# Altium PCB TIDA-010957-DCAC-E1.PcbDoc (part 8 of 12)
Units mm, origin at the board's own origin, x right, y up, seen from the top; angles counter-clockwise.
Board outline 300 x 300 mm, 4 copper layers (Top Layer, Layer 1, Layer 2, Bottom Layer), stack 1.787 mm thick; 1159 components, 619 nets, 3431 pads, 2942 vias.
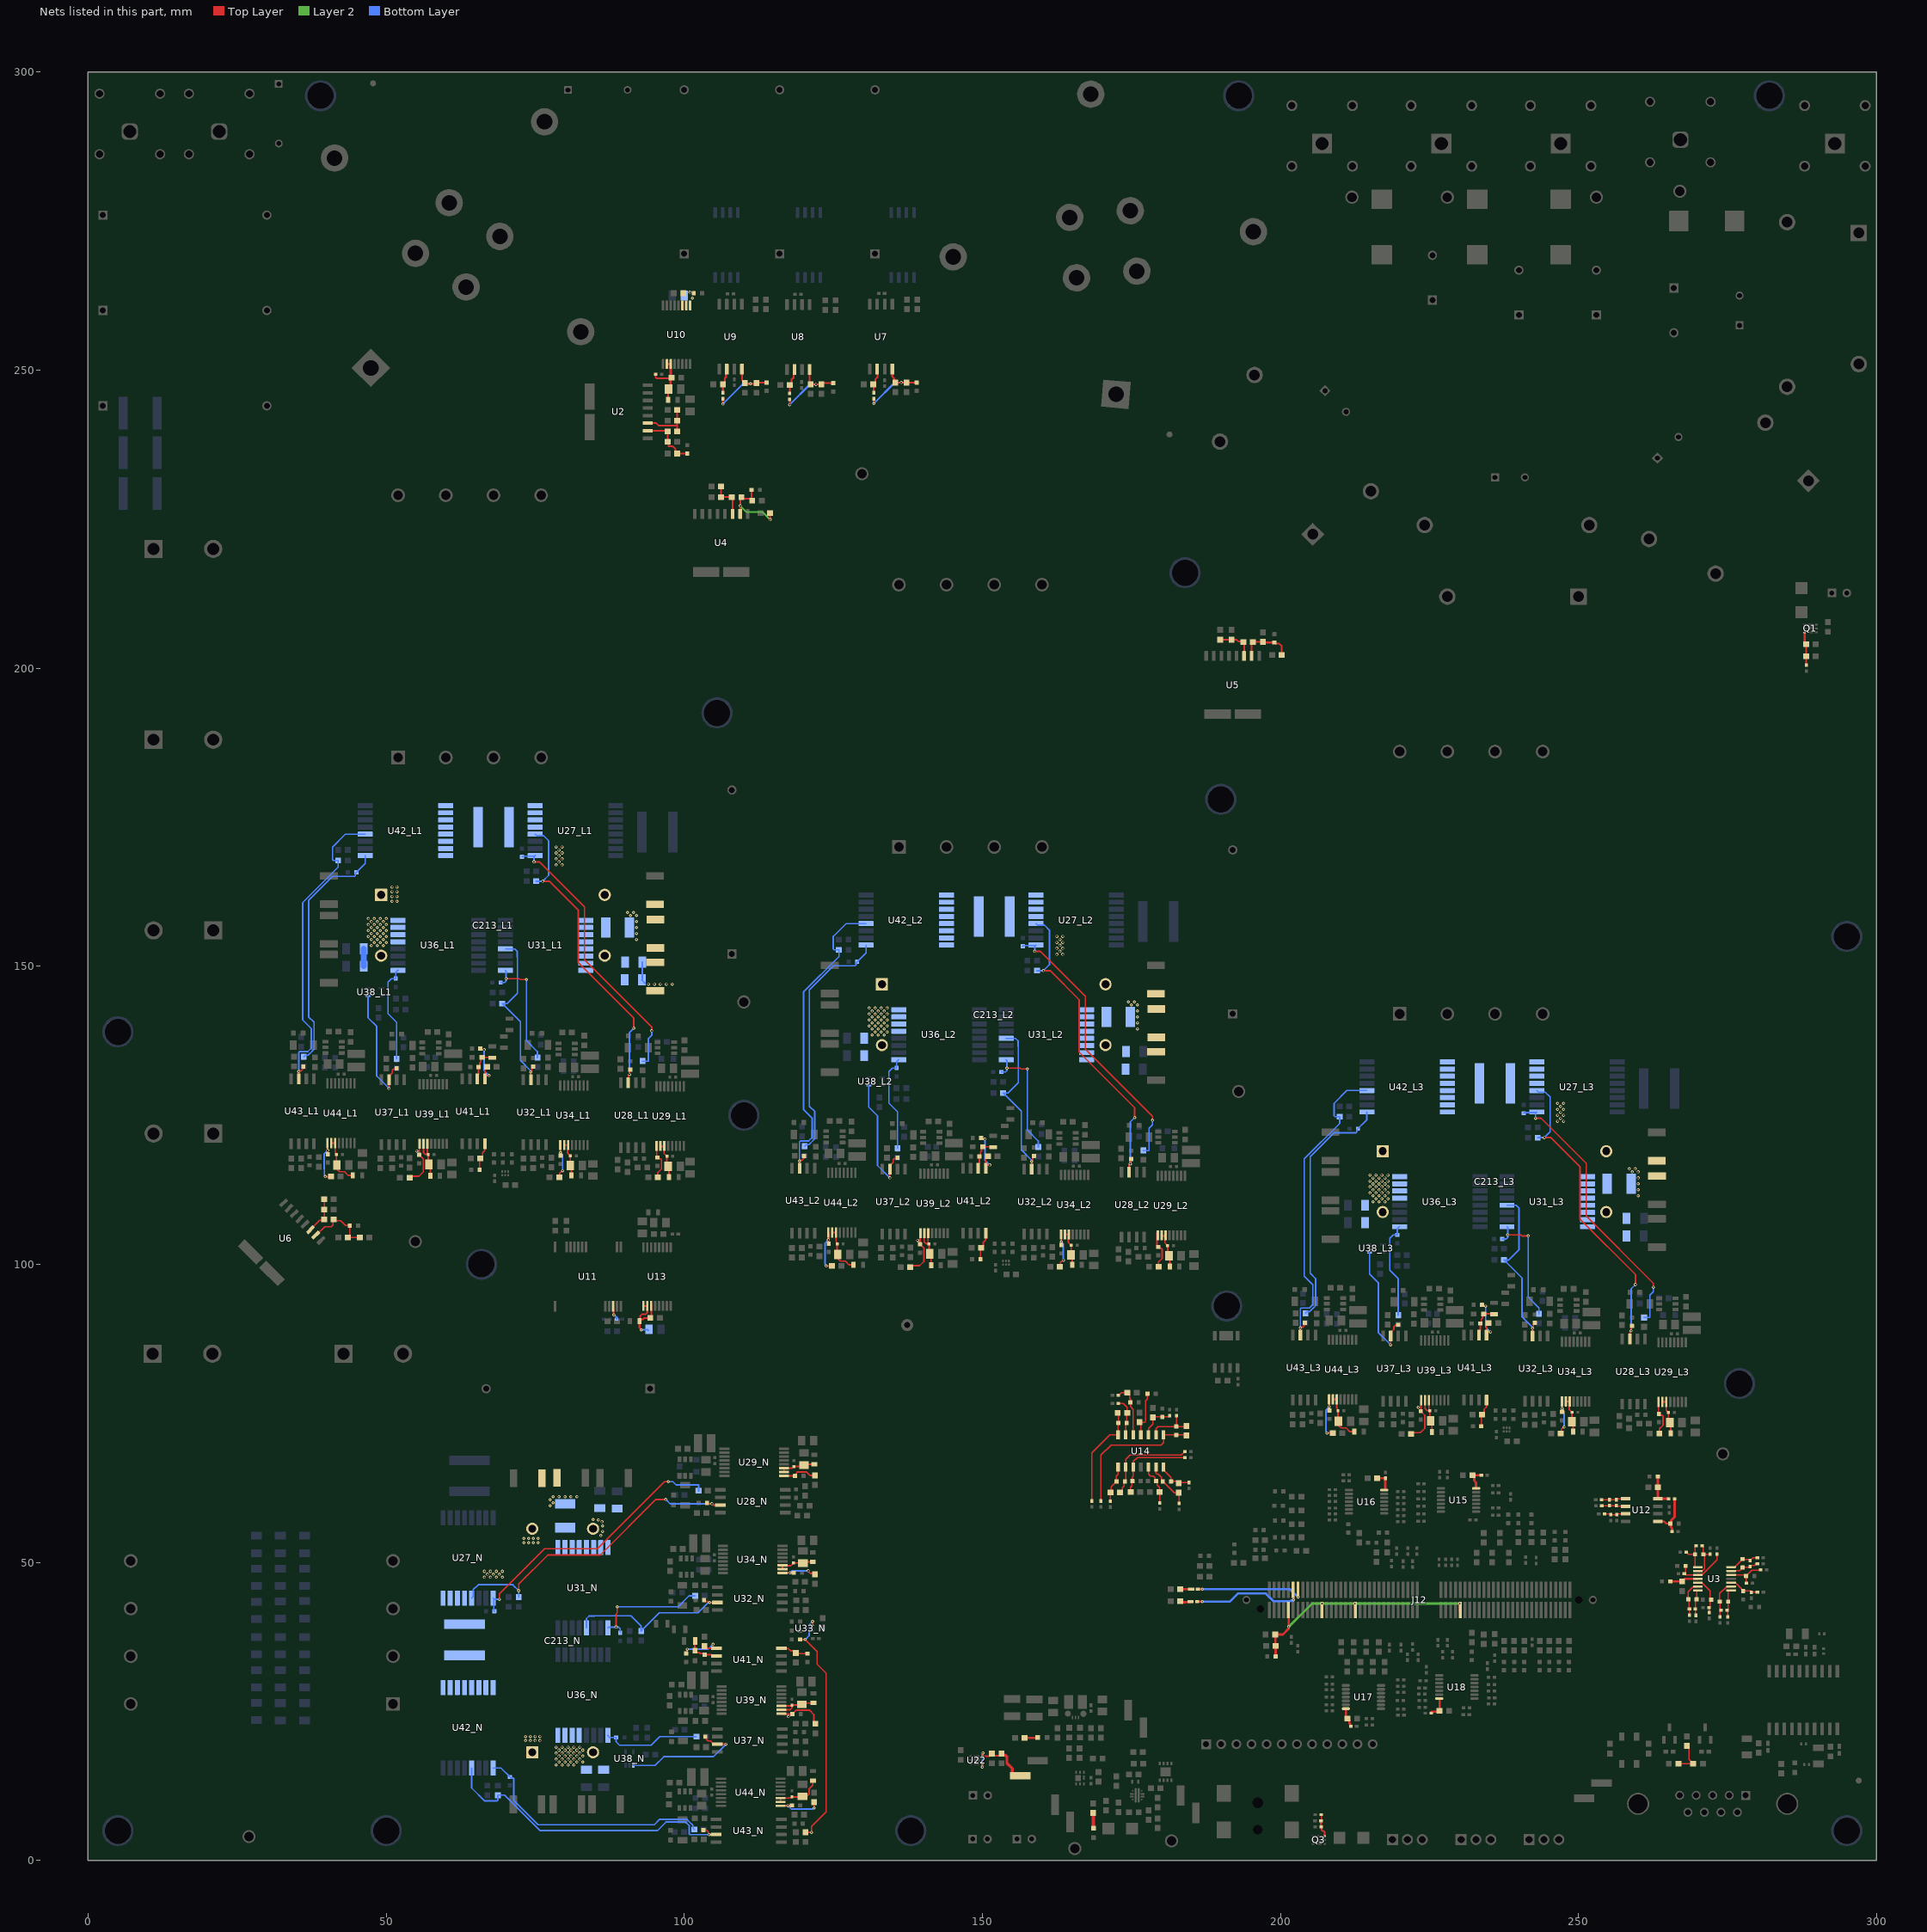
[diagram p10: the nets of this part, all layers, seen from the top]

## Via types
v1: diameter 0.508, hole 0.254, Top Layer to Bottom Layer, tented both sides, 2942 vias

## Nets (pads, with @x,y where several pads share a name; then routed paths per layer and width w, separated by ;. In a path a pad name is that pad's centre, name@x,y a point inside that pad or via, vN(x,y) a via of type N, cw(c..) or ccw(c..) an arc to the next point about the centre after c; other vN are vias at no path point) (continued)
MONITOR_S4_GaN_ISO_N: C206_N.2 R316_N.1 U33_N.6 | length 40.9
  Top Layer w0.254: C206_N.2@119.437,37.075 v1(120.276,37.075) 122.283,35.068 122.283,32.917 123.8,31.4 123.8,8.168 121.358,5.726 v1(121.358,4.718) 120.353,4.718 R316_N.1@120.345,4.725 ; U33_N.6@121.533,39.456 v1(121.533,40.084)
  Bottom Layer w0.254: v1(120.276,37.075) 120.335,37.075 120.936,37.676 120.936,39.488 v1(121.533,40.084)
NetC15_2: C15.2 C16.1 FB1.2 J12.48 J12.84 J12.98 J12.112 | length 42.9
  Top Layer w0.4: C15.2@199.1,37.9 200.4,37.9 201.4,38.9 v1(201.4,39.2) 201.4,41.1 J12.112@201.3,41.2 ; C15.2@199.15,37.85 199.15,36.05 C16.1@199.2,36 ; FB1.2@199.2,34.2 199.2,35.9 C16.1@199.4,36.1 ; J12.98@206.9,42 207,42.1 v1(207,43.1) ; v1(212.5,43.1) 212.525,43.075 212.525,42.025 J12.84@212.55,42 ; J12.48@230.1,41.7 v1(230.1,43.1)
  Layer 2 w0.4: v1(201.4,39.2) 205.3,43.1 v1(212.5,43.1) v1(230.1,43.1)
NetC28_1: C28.1 Q1.3 R96.2 R97.2 | length 5.8
  Top Layer w0.3: C28.1@287.9,204 287.93,204.03 Q1.3@287.93,206 ; R96.2@288.2,200.5 R97.2@288.2,202 288.2,204.1 C28.1@288.3,204.2
NetC29_1: C29.1 R98.1 R100.1 U3.5 | length 6.6
  Top Layer w0.2: U3.5@270,46.6 270.075,46.525 270.795,46.525 272.1,45.22 C29.1@272.1,43.6 ; R100.1@271.9,41.6 R98.1@271.9,42.4 271.95,42.4 272.1,42.55 272.1,43.578 C29.1@272.249,43.726
NetC30_1: C30.1 FB2.2 R99.2 R104.2 U2.4 | length 10.1
  Top Layer w0.3: U2.4@93.875,239.825 97.175,239.825 R104.2@97.3,239.7 ; R104.2@97.1,239.8 R104.2@97.2,239.7 C30.1@97.2,238 97.376,237.824 97.376,237.2 98.1,237.2 98.5,236.8 98.5,236.3 R99.2@98.8,236 FB2.2@100.5,236
NetC32_1: C32.1 R101.1 R103.1 U3.7 | length 4.5
  Top Layer w0.2: R101.1@269.65,40.997 269.65,43.625 C32.1@269.816,43.791 ; C32.1@269.8,43.791 269.8,45.225 269.875,45.3 U3.7@270,45.3
NetC32_2: C32.2 R102.1 R103.2 U3.6 | length 5.9
  Top Layer w0.2: C32.2@268.4,43.791 268.4,45.07 269.205,45.875 269.925,45.875 U3.6@270,45.95 ; C32.2@268.416,43.791 268.55,43.657 268.55,42.25 R103.2@268.6,42.2 R102.1@268.6,41.195
NetC34_1: C34.1 R104.1 R105.2 U2.5 | length 8.5
  Top Layer w0.3: U2.5@94,241.1 95.3,241.1 95.7,240.7 96.53,240.7 96.555,240.675 97.845,240.675 97.87,240.7 98.8,240.7 ; R104.1@98.8,239.7 98.8,240.7 ; C34.1@98.8,243.2 R105.2@98.8,241.5 98.8,240.7
NetC35_1: C35.1 R106.1 R107.1 U3.10 | length 5.2
  Top Layer w0.2: U3.10@275.6,46.6 275.675,46.525 276.395,46.525 277.367,45.552 277.367,45.432 C35.1@277.617,45.182 278.846,45.182 278.996,45.032 R106.1@278.996,44.985 279.011,45 R107.1@280,45
NetC36_1: C36.1 FB3.2 R109.2 R112.2 U4.4 | length 13.3
  Top Layer w0.3: U4.4@109.384,225.875 109.392,225.883 109.392,227.192 v1(109.4,227.2) R112.2@109.4,228.4 ; R112.2@109.5,228.4 111.1,228.4 C36.1@111.3,228.2 ; C36.1@111.2,228.1 C36.1@111.3,228.2 ; FB3.2@111.3,229.9 C36.1@111.3,228.2 ; v1(114.4,224.9) R109.2@114.4,226
  Layer 2 w0.3: v1(109.4,227.2) 110.4,226.2 113.1,226.2 v1(114.4,224.9)
NetC38_1: C38.1 R108.1 R111.1 U3.8 | length 5.1
  Top Layer w0.2: R111.1@274.863,41.95 275.063,42.15 275.063,43.383 C38.1@275.089,43.409 275.089,45.225 275.164,45.3 U3.8@275.6,45.3 ; R111.1@274.9,42 275.05,41.85 R108.1@275.05,40.863
NetC38_2: C38.2 R110.1 R111.2 U3.9 | length 6.3
  Top Layer w0.2: R110.1@273.75,40.863 273.75,43.349 C38.2@273.689,43.409 273.689,44.759 274.805,45.875 275.525,45.875 U3.9@275.6,45.95
NetC40_1: C40.1 R112.1 R113.2 U4.5 | length 6.6
  Top Layer w0.3: C40.1@105.9,230.6 106.2,230.3 R113.2@106.2,228.7 R112.1@108,228.7 ; U4.5@108.114,225.875 R112.1@108.114,228.7
NetC41_1: C41.1 R114.1 R115.1 U3.12 | length 6.7
  Top Layer w0.2: U3.12@275.6,47.9 277.919,47.9 C41.1@278.1,47.719 ; R114.1@278.185,46.5 278.1,46.585 C41.1@278.1,47.719 ; R115.1@280.567,48.7 279.081,48.7 C41.1@278.1,47.719
NetC42_1: C42.1 FB4.2 R117.2 R120.2 U5.4 | length 9.2
  Top Layer w0.3: U5.4@195.175,202.04 195.175,204.575 R120.2@195.3,204.7 ; R120.2@195.5,204.3 195.6,204.4 C42.1@197.1,204.4 ; C42.1@197.1,204.3 FB4.2@199,204.3 199.2,204.1 199.8,204.1 200.2,203.7 R117.2@200.2,202.2
NetC44_1: C44.1 R116.1 R119.1 U3.14 | length 5.3
  Top Layer w0.2: U3.14@275.6,49.2 276.225,49.2 276.3,49.275 276.3,49.313 C44.1@277.537,50.55 277.587,50.5 278.65,50.5 R119.1@278.8,50.35 ; R119.1@278.8,50.3 R119.1@278.8,50.35 ; R116.1@279.993,50.8 279.25,50.8 R119.1@278.8,50.35
NetC44_2: C44.2 R118.1 R119.2 U3.13 | length 4.9
  Top Layer w0.2: U3.13@275.6,48.55 275.675,48.625 277.012,48.625 C44.2@277.537,49.15 278.65,49.15 R119.2@278.8,49.3 278.8,49.35 278.95,49.5 279.496,49.5 279.746,49.75 R118.1@279.993,49.75
NetC46_1: C46.1 R120.1 R121.2 U5.5 | length 6.4
  Top Layer w0.3: R121.2@189.9,204.8 C46.1@191.8,204.8 192.6,204.8 192.9,204.5 R120.1@193.7,204.5 ; R120.1@193.8,204.4 193.905,204.295 U5.5@193.905,202.04 193.905,202.005 U5.5@193.9,202
NetC47_2: C47.2 FB5.2 U3.4 | length 4.8
  Top Layer w0.4: FB5.2@265.4,46.8 C47.2@267.4,46.8 267.4,46.825 267.825,47.25 U3.4@270,47.25
NetC48_1: C48.1 R122.1 R124.1 U3.3 | length 8.9
  Top Layer w0.2: R122.1@267.75,48.119 R122.1@267.8,48.119 ; C48.1@267.95,49.4 267.95,48.269 R122.1@267.8,48.119 ; R124.1@273.2,51.4 273.2,50.38 270.795,47.975 270.075,47.975 U3.3@270,47.9 268.019,47.9 R122.1@267.8,48.119
NetC49_1: C49.1 FB6.2 R123.2 R128.2 U6.4 | length 11.8
  Top Layer w0.2: U6.4@38.192,104.908 38.308,104.908 39.7,106.3 40.8,106.3 41.1,106.6 41.1,107.375 R128.2@41.225,107.5 41.425,107.3 42.4,107.3 43.2,106.5 FB6.2@43.9,106.5 43.9,104.8 R123.2@43.6,104.5 C49.1@45.6,104.5
NetC51_1: C51.1 R125.1 R127.1 U3.1 | length 5.8
  Top Layer w0.2: R125.1@268.05,51.684 268.1,51.684 268.438,51.346 C51.1@269.55,51.346 ; R127.1@269.75,52.807 269.7,52.807 269.55,52.657 269.55,52.607 C51.1@269.55,51.346 ; U3.1@270,49.2 269.625,49.2 269.55,49.275 C51.1@269.55,51.346
NetC51_2: C51.2 R126.1 R127.2 U3.2 | length 6.5
  Top Layer w0.2: U3.2@270,48.55 270.075,48.625 270.795,48.625 271.1,48.93 271.1,51.196 C51.2@270.95,51.346 ; R127.2@270.75,52.807 270.8,52.807 270.95,52.657 C51.2@270.95,51.346 ; R126.1@272.1,51.4 272.046,51.346 C51.2@270.95,51.346
NetC53_1: C53.1 R128.1 R129.2 U6.5 | length 6.4
  Top Layer w0.2: U6.5@37.294,105.807 38.875,107.387 39.512,107.387 R128.1@39.625,107.5 C53.1@39.625,110.9
NetC56_2: C56.2 C57.1 FB7.1 R131.2 U7.8 | length 12.9
  Top Layer w0.3: v1(131.8,244.4) R131.2@131.8,245.2 ; U7.8@134.91,250.15 134.91,248.89 135.2,248.6 C56.2@135.2,247.87 ; C56.2@135.4,247.8 135.5,247.9 v1(136.4,247.9) 137,247.9 FB7.1@139,247.9
  Bottom Layer w0.3: v1(131.8,244.4) 135.3,247.9 v1(136.4,247.9)
NetC60_1: C60.1 R131.1 U7.6 | length 3.8
  Top Layer w0.3: R131.1@131.8,246.2 131.8,247.5 C60.1@131.9,247.6 ; C60.1@131.812,247.687 132.05,247.925 132.05,248.45 132.4,248.8 U7.6@132.4,249.8
NetC63_2: C63.2 C64.1 FB8.1 R133.2 U8.8 | length 12.3
  Top Layer w0.3: v1(117.7,244.2) R133.2@117.7,245.1 ; C63.2@121,247.8 121.04,247.84 U8.8@121.04,250.1 ; C63.2@121.5,247.6 v1(122.1,247.6) ; v1@122.2,247.6 123.017,247.6 C64.1@123.02,247.602 ; C64.1@123.1,247.8 FB8.1@125,247.8
  Bottom Layer w0.3: v1(117.7,244.2) 121.1,247.6 v1(122.1,247.6)
NetC67_1: C67.1 R133.1 U8.6 | length 4.2
  Top Layer w0.3: R133.1@117.7,246.1 C67.1@117.7,247.5 118,247.8 118,248.424 118.176,248.6 118.224,248.6 118.374,248.75 118.374,249.674 U8.6@118.6,249.9
NetC70_2: C70.2 C71.1 FB9.1 R135.2 U9.8 | length 12.6
  Top Layer w0.3: v1(106.5,244.3) 106.5,245.1 R135.2@106.6,245.2 ; U9.8@109.675,250.15 109.675,248.35 110.2,247.825 C70.2@110.2,247.8 ; C70.2@110.5,247.8 110.5,247.725 110.525,247.7 v1(111.1,247.7) C71.1@111.8,247.7 ; C71.1@112.4,247.7 112.4,247.875 112.425,247.9 FB9.1@113.8,247.9
  Bottom Layer w0.3: v1(106.5,244.3) 109.9,247.7 v1(111.1,247.7) v1@111.2,247.7
NetC74_1: C74.1 R135.1 U9.6 | length 3.9
  Top Layer w0.3: R135.1@106.5,246.2 106.5,247.4 C74.1@106.7,247.6 ; C74.1@106.612,247.688 106.85,247.925 106.85,248.65 106.999,248.799 106.999,249.799 U9.6@107.1,249.9
NetC75_1: C75.1 C76.1 FB10.2 U10.9 U10.10 U10.11
  other v1: 101.375,262.079 100.966,263.045
NetC77_1: C77.1 C78.1 L7.1 R136.1 U10.2 U10.3 | length 10
  Top Layer w0.2: C77.1@97.75,248.85 C77.1@97.9,248.7
  Top Layer w0.3: R136.1@95.1,249.3 95.2,249.2 95.2,248.776 95.376,248.6 C77.1@97.7,248.6 ; L7.1@97.3,245 C78.1@97.3,246.6 ; C78.1@97.384,246.8 97.7,247.116 C77.1@97.7,248.6 ; C77.1@97.7,248.7 C77.1@97.7,248.6 ; C77.1@97.9,248.7 97.8,248.6 C77.1@97.7,248.6
  Top Layer w0.4: U10.2@97.1,251 U10.3@97.75,251 C77.1@97.75,248.85
NetC82_1: C82.1 FB16.1 R331.1 U12.8 | length 5.5
  Top Layer w0.45: FB16.1@263.3,64.4 C82.1@263.3,62.6 U12.8@263.3,60.68 R331.1@265.121,60.68
NetC83_2: C83.2 R137.1 R139.1 U12.3 | length 3.6
  Top Layer w0.2: R139.1@254.383,58.14 255.26,58.14 C83.2@255.4,58 R137.1@256.4,58 256.54,58.14 U12.3@257.9,58.14
NetC85_2: C85.2 U11.4 | length 2
  Top Layer w0.3: U11.4@88.154,92.5 88.141,92.486 88.141,91.559 v1(88.2,91.5)
  Bottom Layer w0.3: v1(88.2,91.5) 88.284,91.5 88.684,91.1 88.684,90.816 C85.2@88.7,90.8
NetC86_1: C86.1 R141.1 R142.1 U12.2 | length 4.1
  Top Layer w0.2: R141.1@253.9,59.5 255.477,59.5 ; C86.1@255.405,59.513 R142.1@256.35,59.513 256.453,59.41 U12.2@257.9,59.41
NetC86_2: C86.2 R140.1 R142.2 U12.1 | length 4.2
  Top Layer w0.2: R140.1@253.883,60.513 255.49,60.513 ; C86.2@255.405,60.513 R142.2@256.35,60.513 ; R142.2@256.35,60.53 256.5,60.68 U12.1@257.9,60.68
NetC89_1: C89.1 C90.1 L8.1 U13.9 U13.10 U13.11 | length 10.5
  Top Layer w0.3: v1(92.8,89) 92.8,89.084 92.5,89.384 L8.1@92.5,90.5 92.632,90.632 L8.1@92.632,90.71 ; U13.9@93.163,93.004 93.796,93.004 U13.10@93.8,93 ; U13.10@93.8,92.6 93.8,91.9 93.5,91.6 92.884,91.6 92.632,91.348 L8.1@92.632,90.71 ; C90.1@94.3,91 93.33,91 93.108,90.778 92.7,90.778 L8.1@92.632,90.71 ; C90.1@94.313,91.033 94.5,91.22 U13.11@94.5,93.2
  Bottom Layer w0.3: v1(92.8,89) 93.9,89 C89.1@94,88.9
NetC94_1: C94.1 FB11.2 U14.4 | length 8
  Top Layer w0.2: U14.4@176.586,71.384 176.586,73.269 176.426,73.429 176.497,73.5 177.283,73.5 177.4,73.617 177.4,77.1 177.7,77.4 FB11.2@177.7,78.3
NetC95_2: C95.2 R144.1 R145.1 U14.3 | length 6.2
  Top Layer w0.2: U14.3@177.856,71.384 177.856,72.456 178.6,73.2 R144.1@178.6,74.3 178.7,74.4 C95.2@180.2,74.4 180.204,74.404 181.278,74.404 181.428,74.554 R145.1@181.428,74.604
NetC97_1: C97.1 R147.1 R148.2 U14.2 | length 8.2
  Top Layer w0.2: U14.2@179.126,71.384 179.126,72.426 179.5,72.8 182.503,72.8 C97.1@182.519,72.784 ; R147.1@182.59,74.609 182.59,72.854 C97.1@182.519,72.784 ; R148.2@184.209,72.884 184.109,72.784 C97.1@182.519,72.784
NetC97_2: C97.2 R146.1 R148.1 U14.1 | length 24.1
  Top Layer w0.2: R146.1@169.9,60.3 169.9,68 171.6,69.7 180,69.7 180.396,70.096 U14.1@180.396,71.384 C97.2@182.519,71.384 R148.1@184.109,71.384
NetC98_2: C98.2 R149.1 R150.1 U14.5 | length 9.2
  Top Layer w0.2: R150.1@172.82,78 172.87,78 173.345,78.475 R149.1@174.291,78.475 174.316,78.475 174.691,78.1 174.691,77.509 174.832,77.368 C98.2@174.832,76.829 174.832,76.168 175.316,75.684 U14.5@175.316,71.384
NetC100_1: C100.1 R152.1 R153.2 U14.6 | length 6.5
  Top Layer w0.2: R152.1@172.82,76.663 173.637,76.663 174.295,76.005 R153.2@174.295,75.051 174.215,74.971 C100.1@174.215,73.401 174.046,73.232 U14.6@174.046,71.384
NetC100_2: C100.2 R151.1 R153.1 U14.7 | length 17.5
  Top Layer w0.2: R151.1@168.4,60.244 168.4,68.4 171.384,71.384 U14.7@172.776,71.384 172.776,73.362 C100.2@172.815,73.401 172.815,74.931 R153.1@172.695,75.051
NetC101_2: C101.2 R154.1 R155.1 U14.10 | length 14.3
  Top Layer w0.2: R154.1@174.873,61.784 174.873,62.573 175.1,62.8 175.1,63.549 C101.2@175.176,63.625 175.176,64.276 175.316,64.416 U14.10@175.316,65.984 175.316,66.916 176,67.6 R155.1@184,67.6
NetC103_1: C103.1 R157.1 R158.2 U14.9 | length 16.4
  Top Layer w0.2: R158.2@173.12,61.741 173.125,61.741 173.5,62.116 173.5,62.5 173.8,62.8 173.8,63.462 C103.1@173.92,63.583 174.046,63.709 U14.9@174.046,65.984 174.1,66.037 174.1,67.3 174.8,68 183.4,68 R157.1@184,68.6
NetC103_2: C103.2 R156.1 R158.1 U14.8 | length 6.3
  Top Layer w0.2: R156.1@171.457,60.275 171.457,61.678 R158.1@171.52,61.741 171.6,61.821 171.6,62.662 C103.2@172.52,63.583 172.5,63.603 172.5,64.5 172.776,64.776 U14.8@172.776,65.984
NetC104_2: C104.2 R159.1 R160.1 U14.12 | length 7.1
  Top Layer w0.2: U14.12@177.856,65.984 177.856,64.844 178.2,64.5 178.7,64.5 179,64.2 179,63.782 C104.2@179.157,63.625 179.358,63.424 179.358,62.942 179.7,62.6 R159.1@179.7,61.8 179.765,61.735 R160.1@179.765,59.975
NetC106_1: C106.1 R162.1 R163.2 U14.13 | length 8.3
  Top Layer w0.2: U14.13@179.126,65.984 179.126,64.917 179.243,64.8 179.5,64.8 180.06,64.24 180.06,63.784 C106.1@180.261,63.583 182.195,61.648 183,61.648 R162.1@183,59.9
NetC106_2: C106.2 R161.1 R163.1 U14.14 | length 6.2
  Top Layer w0.2: U14.14@180.396,65.984 180.396,65.509 180.9,65.005 180.9,65 181.661,64.239 C106.2@181.661,63.583 ; C106.2@181.6,63.521 C106.2@181.661,63.583 ; R161.1@184.7,63.4 183.031,63.4 R163.1@182.94,63.309 182.666,63.583 C106.2@181.661,63.583
NetC107_1: C107.1 R164.1 U15.14 | length 3.9
  Top Layer w0.4: C107.1@232.2,64.6 C107.1@232.225,64.6 ; U15.14@232.821,62.402 232.821,63.379 232.5,63.7 232.5,64.325 C107.1@232.225,64.6 ; R164.1@233.7,64.6 C107.1@232.225,64.6
NetC113_1: C113.1 R174.1 U16.14 | length 3.2
  Top Layer w0.4: C113.1@216.2,64.1 R174.1@217.5,64.1 ; U16.14@217.6,62.2 R174.1@217.6,64.1
NetC114_1: C114.1 R175.1 U17.14 | length 3
  Top Layer w0.4: U17.14@211,25.3 211,24.048 C114.1@211.266,23.781 ; C114.1@211.4,23.7 211.566,23.534 211.566,23.034 211.7,22.9 211.7,22.55 211.75,22.5 R175.1@211.8,22.5
NetC125_1: C125.1 R194.1 U18.14 | length 3.4
  Top Layer w0.4: R194.1@225.3,24.9 225.35,24.95 C125.1@226.65,24.95 ; C125.1@226.7,25.1 U18.14@226.7,27.1
NetC138_1: C138.1 C144.1 J18.2 U22.4 U22.6 | length 12.9
  Top Layer w0.2: v1@149.975,15.626 v1(150,15.651) 150.025,15.676 U22.4@150.025,16.176 ; U22.6@150.025,17.476 150.025,17.951 v1(150.1,18.026) ; C144.1@151.287,17.562 151.6,17.875 C144.1@151.6,17.9 ; J18.2@155.293,14.205 J18.2@156.373,14.205
  Top Layer w0.3: U22.4@150.025,16.176 U22.4@150.1,16.176 ; U22.6@150.025,17.476 151.201,17.476 151.287,17.562 C138.1@152.862,17.562
  Top Layer w0.5: C138.1@153.2,17.9 153.2,17.875 153.425,17.65 153.832,17.65 154.125,17.357 154.125,16.3 155,15.425 155,14.498 J18.2@155.293,14.205
  Bottom Layer w0.2: v1(150,15.651) 150,17.842 150.1,17.942 v1(150.1,18.026)
NetC157_2: C157.2 R226.1 R227.2 | length 5.9
  Top Layer w0.2: R226.1@266.75,16.25 R227.2@269.225,16.25 ; C157.2@268.2,19.2 268.526,18.874 268.526,16.949 R227.2@269.225,16.25 ; R227.2@269.25,16.25 R227.2@269.225,16.25
NetC188_L1_2: C188_L1.2 R279_L1.2 U27_L1.9 | length 46.6
  Top Layer w0.254: v1(74.8,167.5) 75.725,167.5 83.288,159.937 83.288,151.073 94.55,139.811 v1(94.55,139.151)
  Bottom Layer w0.254: C188_L1.2@72.801,168.347 72.903,168.448 U27_L1.9@74.898,168.448 ; v1(74.8,167.5) 74.8,168.35 U27_L1.9@74.898,168.448 ; U27_L1.9@75,168.55 U27_L1.9@74.898,168.448 ; R279_L1.2@93,134.073 93.007,134.066 93.975,134.066 93.975,137.834 94.55,138.409 v1(94.55,139.151)
NetC188_L2_2: C188_L2.2 R279_L2.2 U27_L2.9 | length 46.6
  Top Layer w0.254: v1(158.8,152.5) 159.725,152.5 167.288,144.937 167.288,136.073 178.55,124.811 v1(178.55,124.151)
  Bottom Layer w0.254: C188_L2.2@156.801,153.347 156.903,153.448 U27_L2.9@158.898,153.448 ; v1(158.8,152.5) 158.8,153.35 U27_L2.9@158.898,153.448 ; U27_L2.9@159,153.55 U27_L2.9@158.898,153.448 ; R279_L2.2@177,119.073 177.007,119.066 177.975,119.066 177.975,122.834 178.55,123.409 v1(178.55,124.151)
NetC188_L3_2: C188_L3.2 R279_L3.2 U27_L3.9 | length 46.6
  Top Layer w0.254: v1(242.8,124.5) 243.725,124.5 251.288,116.937 251.288,108.073 262.55,96.811 v1(262.55,96.151)
  Bottom Layer w0.254: C188_L3.2@240.801,125.347 240.903,125.448 U27_L3.9@242.898,125.448 ; v1(242.8,124.5) 242.8,125.35 U27_L3.9@242.898,125.448 ; U27_L3.9@243,125.55 U27_L3.9@242.898,125.448 ; R279_L3.2@261,91.073 261.007,91.066 261.975,91.066 261.975,94.834 262.55,95.409 v1(262.55,96.151)
NetC188_N_2: C188_N.2 R279_N.2 U27_N.9 | length 46.6
  Top Layer w0.254: v1(69,43.8) 69,44.725 76.563,52.288 85.427,52.288 96.689,63.55 v1(97.349,63.55)
  Bottom Layer w0.254: U27_N.9@67.95,44 U27_N.9@68.052,43.898 ; C188_N.2@68.153,41.801 68.052,41.903 U27_N.9@68.052,43.898 ; v1(69,43.8) 68.15,43.8 U27_N.9@68.052,43.898 ; v1(97.349,63.55) 98.091,63.55 98.666,62.975 102.434,62.975 102.434,62.007 R279_N.2@102.427,62
NetC189_L1_2: C189_L1.2 R283_L1.2 U27_L1.12 U28_L1.7 | length 53.1
  Top Layer w0.254: v1(76.253,164.25) 77.373,164.25 82.247,159.376 82.247,150.577 91.55,141.273 v1(91.55,139.6) ; U28_L1.7@90.615,130.45 90.615,131.636 v1(90.825,131.846) 90.825,132.524 C189_L1.2@90.967,132.666
  Bottom Layer w0.254: U27_L1.12@75,172.15 75.263,171.887 76.413,171.887 77.25,171.05 77.25,165.247 v1(76.253,164.25) R283_L1.2@75.151,164.25 ; v1(90.825,131.846) 90.825,138.875 v1(91.55,139.6)
NetC189_L2_2: C189_L2.2 R283_L2.2 U27_L2.12 U28_L2.7 | length 53.1
  Top Layer w0.254: v1(160.253,149.25) 161.373,149.25 166.247,144.376 166.247,135.577 175.55,126.273 v1(175.55,124.6) ; U28_L2.7@174.615,115.45 174.615,116.636 v1(174.825,116.846) 174.825,117.524 C189_L2.2@174.967,117.666
  Bottom Layer w0.254: U27_L2.12@159,157.15 159.263,156.887 160.413,156.887 161.25,156.05 161.25,150.247 v1(160.253,149.25) R283_L2.2@159.151,149.25 ; v1(174.825,116.846) 174.825,123.875 v1(175.55,124.6)
NetC189_L3_2: C189_L3.2 R283_L3.2 U27_L3.12 U28_L3.7 | length 53.1
  Top Layer w0.254: v1(244.253,121.25) 245.373,121.25 250.247,116.376 250.247,107.577 259.55,98.273 v1(259.55,96.6) ; U28_L3.7@258.615,87.45 258.615,88.636 v1(258.825,88.846) 258.825,89.524 C189_L3.2@258.967,89.666
  Bottom Layer w0.254: U27_L3.12@243,129.15 243.263,128.887 244.413,128.887 245.25,128.05 245.25,122.247 v1(244.253,121.25) R283_L3.2@243.151,121.25 ; v1(258.825,88.846) 258.825,95.875 v1(259.55,96.6)
NetC189_N_2: C189_N.2 R283_N.2 U27_N.12 U28_N.7 | length 53.1
  Top Layer w0.254: v1(72.25,45.253) 72.25,46.373 77.124,51.247 85.923,51.247 95.227,60.55 v1(96.9,60.55) ; C189_N.2@103.834,59.967 103.976,59.825 v1(104.654,59.825) 104.864,59.615 U28_N.7@106.05,59.615
  Bottom Layer w0.254: U27_N.12@64.35,44 64.613,44.263 64.613,45.413 65.45,46.25 71.253,46.25 v1(72.25,45.253) R283_N.2@72.25,44.151 ; v1(96.9,60.55) 97.625,59.825 v1(104.654,59.825)
NetC196_L1_2: C196_L1.2 R287_L1.1 U29_L1.1 | length 6
  Top Layer w0.254: U29_L1.1@95.375,119.855 95.375,118.027 95.72,117.682 96.011,117.682 96.174,117.519 96.174,115.995 95.563,115.383 R287_L1.1@95.563,114.583
NetC196_L2_2: C196_L2.2 R287_L2.1 U29_L2.1 | length 6.5
  Top Layer w0.254: U29_L2.1@179.3,105.311 179.3,103.102 179.72,102.682 180.011,102.682 180.174,102.519 180.174,100.995 179.563,100.383 R287_L2.1@179.563,99.583
NetC196_L3_2: C196_L3.2 R287_L3.1 U29_L3.1 | length 6.2
  Top Layer w0.254: U29_L3.1@263.425,76.9 C196_L3.2@263.425,74.977 ; C196_L3.2@263.497,74.905 C196_L3.2@263.425,74.977 ; R287_L3.1@263.563,71.583 263.563,72.383 264.174,72.995 264.174,74.519 264.011,74.682 263.72,74.682 C196_L3.2@263.425,74.977
NetC196_N_2: C196_N.2 R287_N.1 U29_N.1 | length 5.9
  Top Layer w0.254: U29_N.1@116.75,64.497 C196_N.2@118.595,64.497 118.818,64.72 118.818,65.011 118.981,65.174 120.505,65.174 121.117,64.563 R287_N.1@121.917,64.563
NetC198_L1_1: C198_L1.1 C199_L1.2 L11_L1.1 U29_L1.2 U29_L1.3 | length 5.5
  Top Layer w0.254: U29_L1.2@96.147,119.75 96.622,119.75 96.622,118.596 C199_L1.2@97.088,118.13 97.088,116.964 97.322,116.73 97.463,116.589 L11_L1.1@97.463,115.058
NetC198_L2_1: C198_L2.1 C199_L2.2 L11_L2.1 U29_L2.2 U29_L2.3 | length 5.5
  Top Layer w0.254: U29_L2.2@180.147,104.75 180.622,104.75 180.622,103.596 C199_L2.2@181.088,103.13 181.088,101.964 181.322,101.73 181.463,101.589 L11_L2.1@181.463,100.058
NetC198_L3_1: C198_L3.1 C199_L3.2 L11_L3.1 U29_L3.2 U29_L3.3 | length 5.8
  Top Layer w0.254: U29_L3.2@264.147,76.75 264.147,76.894 264.153,76.9 264.647,76.9 264.707,76.84 264.707,75.511 C199_L3.2@265.088,75.13 265.088,73.964 265.322,73.73 265.463,73.589 L11_L3.1@265.463,72.058
NetC198_N_1: C198_N.1 C199_N.2 L11_N.1 U29_N.2 U29_N.3 | length 5.6
  Top Layer w0.254: U29_N.2@116.75,65.147 U29_N.3@116.75,65.797 116.759,65.788 118.07,65.788 C199_N.2@118.37,66.088 119.536,66.088 119.77,66.322 119.911,66.463 L11_N.1@121.442,66.463
NetC202_L1_2: C202_L1.2 R292_L1.2 U31_L1.9 | length 20.2
  Top Layer w0.254: v1(70.127,147.925) 72.33,147.925 72.505,147.75 v1(73.55,147.75)
  Bottom Layer w0.254: C202_L1.2@69.207,147.25 69.873,147.25 70.127,147.504 v1(70.127,147.925) 70.127,149.173 U31_L1.9@70,149.3 ; v1(73.55,147.75) 73.55,137.51 75.385,135.675 R292_L1.2@75.385,134.682
NetC202_L2_2: C202_L2.2 R292_L2.2 U31_L2.9 | length 20.2
  Top Layer w0.254: v1(154.127,132.925) 156.33,132.925 156.505,132.75 v1(157.55,132.75)
  Bottom Layer w0.254: C202_L2.2@153.207,132.25 153.873,132.25 154.127,132.504 v1(154.127,132.925) 154.127,134.173 U31_L2.9@154,134.3 ; v1(157.55,132.75) 157.55,122.51 159.385,120.675 R292_L2.2@159.385,119.682
NetC202_L3_2: C202_L3.2 R292_L3.2 U31_L3.9 | length 20.2
  Top Layer w0.254: v1(238.127,104.925) 240.33,104.925 240.505,104.75 v1(241.55,104.75)
  Bottom Layer w0.254: C202_L3.2@237.207,104.25 237.873,104.25 238.127,104.504 v1(238.127,104.925) 238.127,106.173 U31_L3.9@238,106.3 ; v1(241.55,104.75) 241.55,94.51 243.385,92.675 R292_L3.2@243.385,91.682
NetC202_N_2: C202_N.2 R292_N.2 U31_N.9 | length 20.2
  Top Layer w0.254: v1(88.575,39.127) 88.575,41.33 88.75,41.505 v1(88.75,42.55)
  Bottom Layer w0.254: U31_N.9@87.2,39 87.327,39.127 v1(88.575,39.127) 88.996,39.127 89.25,38.873 C202_N.2@89.25,38.207 ; v1(88.75,42.55) 98.99,42.55 100.825,44.385 R292_N.2@101.818,44.385
NetC203_L1_2: C203_L1.2 R294_L1.2 U31_L1.12 U32_L1.7 | length 28.3
  Top Layer w0.254: U32_L1.7@74.275,130.95 v1(74.275,132.253) 74.275,132.321 74.437,132.483 74.437,132.959 C203_L1.2@74.66,133.182
  Bottom Layer w0.254: R294_L1.2@69.49,143.725 R294_L1.2@69.515,143.725 ; U31_L1.12@70,152.9 71.573,152.9 72,152.473 72,151.523 72.031,151.492 72.031,145.453 70.303,143.725 R294_L1.2@69.515,143.725 ; v1(74.275,132.253) 74.275,132.436 72.53,134.181 72.53,140.685 69.863,143.352 69.863,143.377 R294_L1.2@69.515,143.725
NetC203_L2_2: C203_L2.2 R294_L2.2 U31_L2.12 U32_L2.7 | length 28.3
  Top Layer w0.254: U32_L2.7@158.275,115.95 v1(158.275,117.253) 158.275,117.321 158.437,117.483 158.437,117.959 C203_L2.2@158.66,118.182
  Bottom Layer w0.254: R294_L2.2@153.49,128.725 R294_L2.2@153.515,128.725 ; U31_L2.12@154,137.9 155.573,137.9 156,137.473 156,136.523 156.031,136.492 156.031,130.453 154.303,128.725 R294_L2.2@153.515,128.725 ; v1(158.275,117.253) 158.275,117.436 156.53,119.181 156.53,125.685 153.863,128.352 153.863,128.377 R294_L2.2@153.515,128.725
NetC203_L3_2: C203_L3.2 R294_L3.2 U31_L3.12 U32_L3.7 | length 28.3
  Top Layer w0.254: U32_L3.7@242.275,87.95 v1(242.275,89.253) 242.275,89.321 242.437,89.483 242.437,89.959 C203_L3.2@242.66,90.182
  Bottom Layer w0.254: R294_L3.2@237.49,100.725 R294_L3.2@237.515,100.725 ; U31_L3.12@238,109.9 239.573,109.9 240,109.473 240,108.523 240.031,108.492 240.031,102.453 238.303,100.725 R294_L3.2@237.515,100.725 ; v1(242.275,89.253) 242.275,89.436 240.53,91.181 240.53,97.685 237.863,100.352 237.863,100.377 R294_L3.2@237.515,100.725
NetC203_N_2: C203_N.2 R294_N.2 U31_N.12 U32_N.7 | length 28.3
  Top Layer w0.254: C203_N.2@103.318,43.66 103.541,43.437 104.017,43.437 104.179,43.275 v1(104.247,43.275) U32_N.7@105.55,43.275
  Bottom Layer w0.254: U31_N.12@83.6,39 83.6,40.573 84.027,41 84.977,41 85.008,41.031 91.047,41.031 92.775,39.303 R294_N.2@92.775,38.515 ; R294_N.2@92.775,38.49 R294_N.2@92.775,38.515 ; v1(104.247,43.275) 104.064,43.275 102.319,41.53 95.815,41.53 93.148,38.863 93.123,38.863 R294_N.2@92.775,38.515
NetC213_L1_1: C213_L1.1 C215_L1.1 C216_L1.2 R319_L1.2 R320_L1.2 U36_L1.13 U36_L1.14 U36_L1.15 U36_L1.16 U42_L1.1 U42_L1.2 U42_L1.3 U42_L1.4 U42_L1.5 U42_L1.6 U42_L1.7 U42_L1.8 | length 2.9
  Bottom Layer w1: R319_L1.2@46.219,150 R320_L1.2@46.219,152.9
  other v1: 47.525,153.475 48.525,153.475 49.525,153.475 48.025,153.975 49.025,153.975 50.025,153.975 47.525,154.475 48.525,154.475 49.525,154.475 92,154.5 47.025,154.975 48.025,154.975 49.025,154.975 50.025,154.975 47.525,155.475 48.525,155.475 49.525,155.475 92,155.5 47.025,155.975 48.025,155.975 49.025,155.975 50.025,155.975 47.525,156.475 48.525,156.475 49.525,156.475 92,156.5 47.025,156.975 48.025,156.975 49.025,156.975 50.025,156.975 47.525,157.475 48.525,157.475 49.525,157.475 92,157.5 47.025,157.975 48.025,157.975 49.025,157.975 50.025,157.975 91,158.5 92,158.5 90.5,159 91.5,159 51,160.9 51.8,160.9 51,161.7 51.8,161.7 51,162.5 51.8,162.5 51,163.3 51.8,163.3
NetC213_L1_2: C213_L1.2 C215_L1.2 C216_L1.1 R281_L1.1 R282_L1.1 U27_L1.13 U27_L1.14 U27_L1.15 U27_L1.16 U31_L1.1 U31_L1.2 U31_L1.3 U31_L1.4 U31_L1.5 U31_L1.6 U31_L1.7 U31_L1.8
  other v1: 78.5,167 79.5,167 79,167.5 78.5,168 79.5,168 79,168.5 78.5,169 79.5,169 79,169.5 78.5,170 79.5,170
NetC213_L2_1: C213_L2.1 C215_L2.1 C216_L2.2 R319_L2.2 R320_L2.2 U36_L2.13 U36_L2.14 U36_L2.15 U36_L2.16 U42_L2.1 U42_L2.2 U42_L2.3 U42_L2.4 U42_L2.5 U42_L2.6 U42_L2.7 U42_L2.8
  other v1: 131.525,138.475 132.525,138.475 133.525,138.475 132.025,138.975 133.025,138.975 134.025,138.975 131.525,139.475 132.525,139.475 133.525,139.475 176,139.5 131.025,139.975 132.025,139.975 133.025,139.975 134.025,139.975 131.525,140.475 132.525,140.475 133.525,140.475 176,140.5 131.025,140.975 132.025,140.975 133.025,140.975 134.025,140.975 131.525,141.475 132.525,141.475 133.525,141.475 176,141.5 131.025,141.975 132.025,141.975 133.025,141.975 134.025,141.975 131.525,142.475 132.525,142.475 133.525,142.475 176,142.5 131.025,142.975 132.025,142.975 133.025,142.975 134.025,142.975 175,143.5 176,143.5 174.5,144 175.5,144
NetC213_L2_2: C213_L2.2 C215_L2.2 C216_L2.1 R281_L2.1 R282_L2.1 U27_L2.13 U27_L2.14 U27_L2.15 U27_L2.16 U31_L2.1 U31_L2.2 U31_L2.3 U31_L2.4 U31_L2.5 U31_L2.6 U31_L2.7 U31_L2.8
  other v1: 162.5,152 163.5,152 163,152.5 162.5,153 163.5,153 163,153.5 162.5,154 163.5,154 163,154.5 162.5,155 163.5,155
NetC213_L3_1: C213_L3.1 C215_L3.1 C216_L3.2 R319_L3.2 R320_L3.2 U36_L3.13 U36_L3.14 U36_L3.15 U36_L3.16 U42_L3.1 U42_L3.2 U42_L3.3 U42_L3.4 U42_L3.5 U42_L3.6 U42_L3.7 U42_L3.8
  other v1: 215.525,110.475 216.525,110.475 217.525,110.475 216.025,110.975 217.025,110.975 218.025,110.975 215.525,111.475 216.525,111.475 217.525,111.475 260,111.5 215.025,111.975 216.025,111.975 217.025,111.975 218.025,111.975 215.525,112.475 216.525,112.475 217.525,112.475 260,112.5 260,112.5 260,112.5 260,112.5 215.025,112.975 216.025,112.975 217.025,112.975 218.025,112.975 215.525,113.475 216.525,113.475 217.525,113.475 260,113.5 260,113.5 260,113.5 260,113.5 215.025,113.975 216.025,113.975 217.025,113.975 218.025,113.975 215.525,114.475 216.525,114.475 217.525,114.475 260,114.5 260,114.5 260,114.5 260,114.5 215.025,114.975 216.025,114.975 217.025,114.975 218.025,114.975 259,115.5 260,115.5 258.5,116 259.5,116
NetC213_L3_2: C213_L3.2 C215_L3.2 C216_L3.1 R281_L3.1 R282_L3.1 U27_L3.13 U27_L3.14 U27_L3.15 U27_L3.16 U31_L3.1 U31_L3.2 U31_L3.3 U31_L3.4 U31_L3.5 U31_L3.6 U31_L3.7 U31_L3.8
  other v1: 246.5,124 247.5,124 247,124.5 246.5,125 247.5,125 247,125.5 246.5,126 247.5,126 247,126.5 246.5,127 247.5,127
NetC213_N_1: C213_N.1 C215_N.1 C216_N.2 R319_N.2 R320_N.2 U36_N.13 U36_N.14 U36_N.15 U36_N.16 U42_N.1 U42_N.2 U42_N.3 U42_N.4 U42_N.5 U42_N.6 U42_N.7 U42_N.8
  other v1: 78.5,16 79.5,16 80.5,16 81.5,16 79,16.5 80,16.5 81,16.5 82,16.5 83,16.5 78.5,17 79.5,17 80.5,17 81.5,17 82.5,17 79,17.5 80,17.5 81,17.5 82,17.5 83,17.5 78.5,18 79.5,18 80.5,18 81.5,18 82.5,18 79,18.5 80,18.5 81,18.5 82,18.5 83,18.5 78.5,19 79.5,19 80.5,19 81.5,19 82.5,19 73.4,20.1 74.2,20.1 75,20.1 75.8,20.1 73.4,20.8 74.2,20.8 75,20.8 75.8,20.8 77.5,59.5 78,60 77.5,60.5 78,61 79,61 80,61 81,61 82,61
NetC213_N_2: C213_N.2 C215_N.2 C216_N.1 R281_N.1 R282_N.1 U27_N.13 U27_N.14 U27_N.15 U27_N.16 U31_N.1 U31_N.2 U31_N.3 U31_N.4 U31_N.5 U31_N.6 U31_N.7 U31_N.8
  other v1: 66.5,47.5 67.5,47.5 68.5,47.5 69.5,47.5 67,48 68,48 69,48 66.5,48.5 67.5,48.5 68.5,48.5 69.5,48.5 73.1,53.3 73.9,53.3 74.7,53.3 75.5,53.3 73.1,54 73.9,54 74.7,54 75.5,54 86,54.5 86.3,55.2 86.3,56.1 86.2,56.8 85.6,57.1 84.7,57.2
NetC219_L1_2: C219_L1.2 R298_L1.1 U34_L1.1 | length 6.5
  Top Layer w0.254: R298_L1.1@79.025,114.583 79.121,114.68 79.121,115.308 79.515,115.702 v1(79.584,115.702) ; U34_L1.1@79.225,120 79.238,119.987 v1(79.238,118.782) 79.238,118.142 C219_L1.2@79.25,118.13
  Bottom Layer w0.254: v1(79.238,118.782) 79.238,118.713 79.584,118.367 v1(79.584,115.702)
NetC219_L2_2: C219_L2.2 R298_L2.1 U34_L2.1 | length 6.5
  Top Layer w0.254: R298_L2.1@163.025,99.583 163.121,99.68 163.121,100.308 163.515,100.702 v1(163.584,100.702) ; U34_L2.1@163.225,105 163.238,104.988 v1(163.238,103.782) 163.238,103.142 C219_L2.2@163.25,103.13
  Bottom Layer w0.254: v1(163.238,103.782) 163.238,103.713 163.584,103.367 v1(163.584,100.702)
NetC219_L3_2: C219_L3.2 R298_L3.1 U34_L3.1 | length 6.5
  Top Layer w0.254: R298_L3.1@247.025,71.583 247.121,71.68 247.121,72.308 247.515,72.702 v1(247.584,72.702) ; U34_L3.1@247.225,77 247.238,76.988 v1(247.238,75.782) 247.238,75.142 C219_L3.2@247.25,75.13
  Bottom Layer w0.254: v1(247.238,75.782) 247.238,75.713 247.584,75.367 v1(247.584,72.702)
NetC219_N_2: C219_N.2 R298_N.1 U34_N.1 | length 6.5
  Top Layer w0.254: U34_N.1@116.5,48.225 116.513,48.238 v1(117.718,48.238) 118.358,48.238 C219_N.2@118.37,48.25 ; v1(120.798,48.584) 120.798,48.515 121.192,48.121 121.82,48.121 R298_N.1@121.917,48.025
  Bottom Layer w0.254: v1(117.718,48.238) 117.787,48.238 118.133,48.584 v1(120.798,48.584)
NetC221_L1_1: C221_L1.1 C222_L1.2 L13_L1.1 U34_L1.2 U34_L1.3 | length 6
  Top Layer w0.254: U34_L1.2@79.875,120 U34_L1.3@80.525,120 80.447,119.922 80.447,118.914 80.444,118.911 80.444,118.632 C222_L1.2@80.894,118.182 80.894,116.598 C221_L1.1@80.884,116.588 81.094,116.379 L13_L1.1@81.094,114.934
NetC221_L2_1: C221_L2.1 C222_L2.2 L13_L2.1 U34_L2.2 U34_L2.3 | length 6
  Top Layer w0.254: U34_L2.2@163.875,105 U34_L2.3@164.525,105 164.447,104.922 164.447,103.914 164.444,103.911 164.444,103.632 C222_L2.2@164.894,103.182 164.894,101.598 C221_L2.1@164.884,101.588 165.094,101.379 L13_L2.1@165.094,99.934
NetC221_L3_1: C221_L3.1 C222_L3.2 L13_L3.1 U34_L3.2 U34_L3.3 | length 6
  Top Layer w0.254: U34_L3.2@247.875,77 U34_L3.3@248.525,77 248.447,76.922 248.447,75.914 248.444,75.911 248.444,75.632 C222_L3.2@248.894,75.182 248.894,73.598 C221_L3.1@248.884,73.588 249.094,73.379 L13_L3.1@249.094,71.934
NetC221_N_1: C221_N.1 C222_N.2 L13_N.1 U34_N.2 U34_N.3 | length 6
  Top Layer w0.254: U34_N.2@116.5,48.875 U34_N.3@116.5,49.525 116.578,49.447 117.586,49.447 117.589,49.444 117.868,49.444 C222_N.2@118.318,49.894 119.902,49.894 C221_N.1@119.912,49.884 120.121,50.094 L13_N.1@121.566,50.094
NetC226_L1_2: C226_L1.2 R303_L1.2 U36_L1.9 | length 16.6
  Bottom Layer w0.254: R303_L1.2@51.764,134.466 51.764,140.594 50.33,142.028 50.33,147.347 50.908,147.925 C226_L1.2@51.622,147.925 51.622,149.002 51.92,149.3 U36_L1.9@52,149.3
NetC226_L2_2: C226_L2.2 R303_L2.2 U36_L2.9 | length 16.6
  Bottom Layer w0.254: R303_L2.2@135.764,119.466 135.764,125.594 134.33,127.028 134.33,132.347 134.908,132.925 C226_L2.2@135.622,132.925 135.622,134.002 135.92,134.3 U36_L2.9@136,134.3
NetC226_L3_2: C226_L3.2 R303_L3.2 U36_L3.9 | length 16.6
  Bottom Layer w0.254: R303_L3.2@219.764,91.466 219.764,97.594 218.33,99.028 218.33,104.347 218.908,104.925 C226_L3.2@219.622,104.925 219.622,106.002 219.92,106.3 U36_L3.9@220,106.3
NetC226_N_2: C226_N.2 R303_N.2 U36_N.9 | length 16.6
  Bottom Layer w0.254: U36_N.9@87.2,21 87.2,20.92 87.498,20.622 C226_N.2@88.575,20.622 88.575,19.908 89.153,19.33 94.472,19.33 95.906,20.764 R303_N.2@102.034,20.764
NetC227_L1_2: C227_L1.2 U37_L1.7 U38_L1.1 | length 21.2
  Top Layer w0.25: v1(50.494,129.5) U37_L1.7@50.494,130.95 50.494,130.994 U37_L1.7@50.5,131
  Top Layer w0.254: U37_L1.7@50.494,131 50.494,131.55 51.039,132.095 51.039,132.541 51.263,132.765 51.563,132.765 C227_L1.2@51.764,132.966
  Bottom Layer w0.254: U38_L1.1@46.953,145.025 46.953,141.376 48.419,139.909 48.419,131.575 v1(50.494,129.5)
NetC227_L2_2: C227_L2.2 U37_L2.7 U38_L2.1 | length 21.2
  Top Layer w0.25: v1(134.494,114.5) U37_L2.7@134.494,115.95 134.494,115.994 U37_L2.7@134.5,116
  Top Layer w0.254: U37_L2.7@134.494,116 134.494,116.55 135.039,117.095 135.039,117.541 135.263,117.765 135.563,117.765 C227_L2.2@135.764,117.966
  Bottom Layer w0.254: U38_L2.1@130.953,130.025 130.953,126.376 132.419,124.909 132.419,116.575 v1(134.494,114.5)
NetC227_L3_2: C227_L3.2 U37_L3.7 U38_L3.1 | length 21.2
  Top Layer w0.25: v1(218.494,86.5) U37_L3.7@218.494,87.95 218.494,87.994 U37_L3.7@218.5,88
  Top Layer w0.254: U37_L3.7@218.494,88 218.494,88.55 219.039,89.095 219.039,89.541 219.263,89.765 219.563,89.765 C227_L3.2@219.764,89.966
  Bottom Layer w0.254: U38_L3.1@214.953,102.025 214.953,98.376 216.419,96.909 216.419,88.575 v1(218.494,86.5)
NetC227_N_2: C227_N.2 U37_N.7 U38_N.1 | length 21.2
  Top Layer w0.25: U37_N.7@105.5,19.5 105.506,19.494 U37_N.7@105.55,19.494 v1(107,19.494)
  Top Layer w0.254: C227_N.2@103.534,20.764 103.735,20.563 103.735,20.263 103.959,20.039 104.405,20.039 104.95,19.494 U37_N.7@105.5,19.494
  Bottom Layer w0.254: U38_N.1@91.475,15.953 95.124,15.953 96.591,17.419 104.925,17.419 v1(107,19.494)
NetC236_L1_2: C236_L1.2 R308_L1.1 U39_L1.1 | length 8.1
  Top Layer w0.254: R308_L1.1@54.004,114.417 54.352,114.765 55.485,114.765 56.218,115.498 56.218,117.678 C236_L1.2@55.541,118.355 55.575,118.39 55.575,119.011 ; v1(55.129,119.011) 55.575,119.011 ; U39_L1.1@55.61,120.208 55.575,120.174 55.575,119.011
NetC236_L2_2: C236_L2.2 R308_L2.1 U39_L2.1 | length 8.1
  Top Layer w0.254: R308_L2.1@138.004,99.417 138.352,99.765 139.485,99.765 140.218,100.498 140.218,102.678 C236_L2.2@139.541,103.355 139.575,103.39 139.575,104.011 ; v1(139.129,104.011) 139.575,104.011 ; U39_L2.1@139.61,105.208 139.575,105.174 139.575,104.011
NetC236_L3_2: C236_L3.2 R308_L3.1 U39_L3.1 | length 8.1
  Top Layer w0.254: R308_L3.1@222.004,71.417 222.352,71.765 223.485,71.765 224.218,72.498 224.218,74.678 C236_L3.2@223.541,75.355 223.575,75.39 223.575,76.011 ; v1(223.129,76.011) 223.575,76.011 ; U39_L3.1@223.61,77.208 223.575,77.174 223.575,76.011
NetC236_N_2: C236_N.2 R308_N.1 U39_N.1 | length 8.1
  Top Layer w0.254: U39_N.1@116.292,24.61 116.326,24.575 117.489,24.575 ; v1(117.489,24.129) 117.489,24.575 ; R308_N.1@122.083,23.004 121.735,23.352 121.735,24.485 121.002,25.218 118.822,25.218 C236_N.2@118.145,24.541 118.11,24.575 117.489,24.575
NetC238_L1_1: C238_L1.1 C239_L1.2 L15_L1.1 U39_L1.2 U39_L1.3 | length 7.6
  Top Layer w0.254: U39_L1.2@56.26,120.208 56.26,118.782 56.61,118.432 C239_L1.2@57.06,118.432 ; U39_L1.3@56.91,120.208 56.91,118.582 C239_L1.2@57.06,118.432 ; L15_L1.1@57.41,115.142 57.41,116.727 57.182,116.955 57.06,117.077 C239_L1.2@57.06,118.432
NetC238_L2_1: C238_L2.1 C239_L2.2 L15_L2.1 U39_L2.2 U39_L2.3 | length 7.6
  Top Layer w0.254: U39_L2.2@140.26,105.208 140.26,103.782 140.61,103.432 C239_L2.2@141.06,103.432 ; U39_L2.3@140.91,105.208 140.91,103.582 C239_L2.2@141.06,103.432 ; L15_L2.1@141.41,100.142 141.41,101.727 141.182,101.955 141.06,102.077 C239_L2.2@141.06,103.432
NetC238_L3_1: C238_L3.1 C239_L3.2 L15_L3.1 U39_L3.2 U39_L3.3 | length 7.6
  Top Layer w0.254: U39_L3.2@224.26,77.208 224.26,75.782 224.61,75.432 C239_L3.2@225.06,75.432 ; U39_L3.3@224.91,77.208 224.91,75.582 C239_L3.2@225.06,75.432 ; L15_L3.1@225.41,72.142 225.41,73.727 225.182,73.955 225.06,74.077 C239_L3.2@225.06,75.432
NetC238_N_1: C238_N.1 C239_N.2 L15_N.1 U39_N.2 U39_N.3 | length 7.6
  Top Layer w0.254: U39_N.2@116.292,25.26 117.718,25.26 118.068,25.61 C239_N.2@118.068,26.06 ; U39_N.3@116.292,25.91 117.918,25.91 C239_N.2@118.068,26.06 ; L15_N.1@121.358,26.41 119.773,26.41 119.545,26.182 119.423,26.06 C239_N.2@118.068,26.06
NetC240_L1_1: C240_L1.1 FB14_L1.2 U41_L1.8 | length 4.7
  Top Layer w0.254: FB14_L1.2@65.689,115.842 65.689,117.675 C240_L1.1@65.8,117.786 65.825,117.786 66.173,118.134 66.173,118.692 66.557,119.076 66.557,120.192 U41_L1.8@66.574,120.208
NetC240_L2_1: C240_L2.1 FB14_L2.2 U41_L2.8 | length 4.7
  Top Layer w0.254: FB14_L2.2@149.689,100.842 149.689,102.675 C240_L2.1@149.8,102.786 149.825,102.786 150.173,103.134 150.173,103.692 150.557,104.076 150.557,105.192 U41_L2.8@150.574,105.208
NetC240_L3_1: C240_L3.1 FB14_L3.2 U41_L3.8 | length 4.7
  Top Layer w0.254: FB14_L3.2@233.689,72.842 233.689,74.675 C240_L3.1@233.8,74.786 233.825,74.786 234.173,75.134 234.173,75.692 234.557,76.076 234.557,77.192 U41_L3.8@234.574,77.208
NetC240_N_1: C240_N.1 FB14_N.2 U41_N.8 | length 4.7
  Top Layer w0.254: U41_N.8@116.292,35.574 116.308,35.557 117.424,35.557 117.808,35.173 118.366,35.173 118.714,34.825 C240_N.1@118.714,34.8 118.825,34.689 FB14_N.2@120.658,34.689
NetC241_L1_1: C241_L1.1 FB15_L1.1 U41_L1.1 | length 8.3
  Top Layer w0.254: FB15_L1.1@65.7,135.984 v1(66.44,135.984) ; U41_L1.1@66.574,131.108 U41_L1.1@66.574,131.484 ; C241_L1.1@66.925,133.116 66.922,133.116 66.574,132.768 U41_L1.1@66.574,131.484 ; v1(67.25,131.657) 66.747,131.657 U41_L1.1@66.574,131.484
  Bottom Layer w0.254: v1(66.44,135.984) 66.44,132.466 v1(67.25,131.657)
NetC241_L2_1: C241_L2.1 FB15_L2.1 U41_L2.1 | length 8.3
  Top Layer w0.254: FB15_L2.1@149.7,120.984 v1(150.44,120.984) ; U41_L2.1@150.574,116.108 U41_L2.1@150.574,116.484 ; C241_L2.1@150.925,118.116 150.922,118.116 150.574,117.768 U41_L2.1@150.574,116.484 ; v1(151.25,116.657) 150.747,116.657 U41_L2.1@150.574,116.484
  Bottom Layer w0.254: v1(150.44,120.984) 150.44,117.466 v1(151.25,116.657)
NetC241_L3_1: C241_L3.1 FB15_L3.1 U41_L3.1 | length 8.3
  Top Layer w0.254: FB15_L3.1@233.7,92.984 v1(234.44,92.984) ; U41_L3.1@234.574,88.108 U41_L3.1@234.574,88.484 ; C241_L3.1@234.925,90.116 234.922,90.116 234.574,89.768 U41_L3.1@234.574,88.484 ; v1(235.25,88.657) 234.747,88.657 U41_L3.1@234.574,88.484
  Bottom Layer w0.254: v1(234.44,92.984) 234.44,89.466 v1(235.25,88.657)
NetC241_N_1: C241_N.1 FB15_N.1 U41_N.1 | length 8.3
  Top Layer w0.254: FB15_N.1@100.516,34.7 v1(100.516,35.44) ; C241_N.1@103.384,35.925 103.384,35.922 103.732,35.574 U41_N.1@105.016,35.574 ; v1(104.843,36.25) 104.843,35.747 U41_N.1@105.016,35.574 ; U41_N.1@105.392,35.574 U41_N.1@105.016,35.574
  Bottom Layer w0.254: v1(100.516,35.44) 104.034,35.44 v1(104.843,36.25)
NetC242_L1_2: C242_L1.2 R312_L1.1 R315_L1.2 U41_L1.2 | length 5.6
  Top Layer w0.254: U41_L1.2@65.304,131.108 65.304,131.708 65.507,131.911 C242_L1.2@65.507,133.082 65.708,133.284 65.708,133.813 65.884,133.989 65.884,134.409 66.185,134.711 67.801,134.711 R312_L1.1@67.829,134.74
NetC242_L2_2: C242_L2.2 R312_L2.1 R315_L2.2 U41_L2.2 | length 5.6
  Top Layer w0.254: U41_L2.2@149.304,116.108 149.304,116.708 149.507,116.911 C242_L2.2@149.507,118.082 149.708,118.284 149.708,118.813 149.884,118.989 149.884,119.409 150.185,119.711 151.801,119.711 R312_L2.1@151.829,119.74
NetC242_L3_2: C242_L3.2 R312_L3.1 R315_L3.2 U41_L3.2 | length 5.6
  Top Layer w0.254: U41_L3.2@233.304,88.108 233.304,88.708 233.507,88.911 C242_L3.2@233.507,90.082 233.708,90.284 233.708,90.813 233.884,90.989 233.884,91.409 234.185,91.711 235.801,91.711 R312_L3.1@235.829,91.74
NetC242_N_2: C242_N.2 R312_N.1 R315_N.2 U41_N.2 | length 5.6
  Top Layer w0.254: R312_N.1@101.76,36.829 101.789,36.801 101.789,35.185 102.091,34.884 102.511,34.884 102.687,34.708 103.216,34.708 C242_N.2@103.418,34.507 104.589,34.507 104.792,34.304 U41_N.2@105.392,34.304
NetC245_L1_2: C245_L1.2 R317_L1.2 U42_L1.9 | length 41.2
  Bottom Layer w0.254: R317_L1.2@36.2,134.798 36.468,135.066 36.908,135.066 37.601,135.759 37.601,135.767 37.9,136.066 37.9,140.6 37,141.5 37,161.03 41.043,165.073 44.057,165.073 44.677,165.073 44.826,165.222 44.826,165.576 46.5,167.25 U42_L1.9@46.5,168.55
NetC245_L2_2: C245_L2.2 R317_L2.2 U42_L2.9 | length 41.2
  Bottom Layer w0.254: R317_L2.2@120.2,119.798 120.468,120.066 120.908,120.066 121.601,120.759 121.601,120.767 121.9,121.066 121.9,125.6 121,126.5 121,146.03 125.043,150.073 128.057,150.073 128.677,150.073 128.826,150.222 128.826,150.576 130.5,152.25 U42_L2.9@130.5,153.55
NetC245_L3_2: C245_L3.2 R317_L3.2 U42_L3.9 | length 41.2
  Bottom Layer w0.254: R317_L3.2@204.2,91.798 204.468,92.066 204.908,92.066 205.601,92.759 205.601,92.767 205.9,93.066 205.9,97.6 205,98.5 205,118.03 209.043,122.073 212.057,122.073 212.677,122.073 212.826,122.222 212.826,122.576 214.5,124.25 U42_L3.9@214.5,125.55
NetC245_N_2: C245_N.2 R317_N.2 U42_N.9 | length 41.2
  Bottom Layer w0.254: U42_N.9@67.95,15.5 69.25,15.5 70.924,13.826 71.278,13.826 71.427,13.677 71.427,13.057 ; 71.427,13.057 71.427,10.043 75.47,6 95,6 95.9,6.9 100.434,6.9 100.733,6.601 100.741,6.601 101.434,5.908 101.434,5.468 R317_N.2@101.702,5.2
NetC246_L1_2: C246_L1.2 R321_L1.2 U42_L1.12 U43_L1.7 | length 52.3
  Top Layer w0.254: U43_L1.7@35.343,131.126 35.343,132.299 35.492,132.448 35.768,132.448 36.075,132.756 36.075,133.246 C246_L1.2@36.111,133.282
  Bottom Layer w0.254: v1(35.343,132.334) 35.343,135.533 35.492,135.682 36.873,135.682 37.446,136.255 37.446,139.554 36,141 36,160.672 41.95,166.622 R321_L1.2@41.95,167.75 41.149,167.75 41,167.899 41,170 43.15,172.15 U42_L1.12@46.5,172.15
NetC246_L2_2: C246_L2.2 R321_L2.2 U42_L2.12 U43_L2.7 | length 52.3
  Top Layer w0.254: U43_L2.7@119.343,116.126 119.343,117.299 119.492,117.448 119.768,117.448 120.075,117.756 120.075,118.246 C246_L2.2@120.111,118.282
  Bottom Layer w0.254: v1(119.343,117.334) 119.343,120.533 119.492,120.682 120.873,120.682 121.446,121.255 121.446,124.554 120,126 120,145.672 125.95,151.622 R321_L2.2@125.95,152.75 125.149,152.75 125,152.899 125,155 127.15,157.15 U42_L2.12@130.5,157.15
NetC246_L3_2: C246_L3.2 R321_L3.2 U42_L3.12 U43_L3.7 | length 52.3
  Top Layer w0.254: U43_L3.7@203.343,88.126 203.343,89.299 203.492,89.448 203.768,89.448 204.075,89.756 204.075,90.246 C246_L3.2@204.111,90.282
  Bottom Layer w0.254: v1(203.343,89.334) 203.343,92.533 203.492,92.682 204.873,92.682 205.446,93.255 205.446,96.554 204,98 204,117.672 209.95,123.622 R321_L3.2@209.95,124.75 209.149,124.75 209,124.899 209,127 211.15,129.15 U42_L3.12@214.5,129.15
NetC246_N_2: C246_N.2 R321_N.2 U42_N.12 U43_N.7 | length 52.3
  Top Layer w0.254: C246_N.2@103.218,5.111 103.254,5.075 103.744,5.075 104.052,4.768 104.052,4.492 104.201,4.343 U43_N.7@105.374,4.343
  Bottom Layer w0.254: U42_N.12@64.35,15.5 64.35,12.15 66.5,10 68.601,10 68.75,10.149 R321_N.2@68.75,10.95 69.878,10.95 75.828,5 95.5,5 96.946,6.446 100.245,6.446 100.818,5.873 100.818,4.492 100.967,4.343 v1(104.166,4.343)
NetC253_L1_2: C253_L1.2 R325_L1.1 U44_L1.1 | length 7.6
  Top Layer w0.254: v1(39.801,114.709) R325_L1.1@40.769,114.709 ; U44_L1.1@40.154,120.338 40.191,120.301 v1(40.191,119.112) 40.191,118.492 C253_L1.2@40.228,118.455
  Bottom Layer w0.254: v1(39.801,114.709) 39.801,114.776 39.629,114.947 39.629,115.98 39.62,115.989 39.62,118.541 v1(40.191,119.112)
NetC253_L2_2: C253_L2.2 R325_L2.1 U44_L2.1 | length 7.6
  Top Layer w0.254: v1(123.801,99.709) R325_L2.1@124.769,99.709 ; U44_L2.1@124.154,105.338 124.191,105.301 v1(124.191,104.112) 124.191,103.492 C253_L2.2@124.228,103.455
  Bottom Layer w0.254: v1(123.801,99.709) 123.801,99.776 123.629,99.947 123.629,100.98 123.62,100.989 123.62,103.541 v1(124.191,104.112)
NetC253_L3_2: C253_L3.2 R325_L3.1 U44_L3.1 | length 7.6
  Top Layer w0.254: v1(207.801,71.709) R325_L3.1@208.769,71.709 ; U44_L3.1@208.154,77.338 208.191,77.301 v1(208.191,76.112) 208.191,75.492 C253_L3.2@208.228,75.455
  Bottom Layer w0.254: v1(207.801,71.709) 207.801,71.776 207.629,71.947 207.629,72.98 207.62,72.989 207.62,75.541 v1(208.191,76.112)
NetC253_N_2: C253_N.2 R325_N.1 U44_N.1 | length 7.6
  Top Layer w0.254: U44_N.1@116.162,9.154 116.199,9.191 v1(117.388,9.191) 118.008,9.191 C253_N.2@118.045,9.228 ; v1(121.791,8.801) R325_N.1@121.791,9.769
  Bottom Layer w0.254: v1(117.388,9.191) 117.959,8.62 120.511,8.62 120.52,8.629 121.553,8.629 121.724,8.801 v1(121.791,8.801)
NetC255_L1_1: C255_L1.1 C256_L1.2 L17_L1.1 U44_L1.2 U44_L1.3 | length 8.2
  Top Layer w0.254: U44_L1.2@40.804,120.338 U44_L1.3@41.454,120.338 41.454,118.959 41.53,118.882 41.53,118.555 C256_L1.2@41.653,118.432 41.653,116.743 C255_L1.1@41.738,116.659 41.753,116.643 41.753,115.934 42.156,115.532 43.022,115.532 43.636,114.917 L17_L1.1@44.4,114.917
NetC255_L2_1: C255_L2.1 C256_L2.2 L17_L2.1 U44_L2.2 U44_L2.3 | length 8.2
  Top Layer w0.254: U44_L2.2@124.804,105.338 U44_L2.3@125.454,105.338 125.454,103.959 125.53,103.882 125.53,103.555 C256_L2.2@125.653,103.432 125.653,101.743 C255_L2.1@125.738,101.659 125.753,101.643 125.753,100.934 126.156,100.532 127.022,100.532 127.636,99.917 L17_L2.1@128.4,99.917
NetC255_L3_1: C255_L3.1 C256_L3.2 L17_L3.1 U44_L3.2 U44_L3.3 | length 8.2
  Top Layer w0.254: U44_L3.2@208.804,77.338 U44_L3.3@209.454,77.338 209.454,75.959 209.53,75.882 209.53,75.555 C256_L3.2@209.653,75.432 209.653,73.743 C255_L3.1@209.738,73.659 209.753,73.643 209.753,72.934 210.156,72.532 211.022,72.532 211.636,71.917 L17_L3.1@212.4,71.917
NetC255_N_1: C255_N.1 C256_N.2 L17_N.1 U44_N.2 U44_N.3 | length 8.2
  Top Layer w0.254: U44_N.2@116.162,9.804 U44_N.3@116.162,10.454 117.541,10.454 117.618,10.53 117.945,10.53 C256_N.2@118.068,10.653 119.757,10.653 C255_N.1@119.841,10.738 119.857,10.753 120.566,10.753 120.968,11.156 120.968,12.022 121.583,12.636 L17_N.1@121.583,13.4
NetC261_1: C261.1 Q3.3 R329.2 R330.2 | length 3.9
  Top Layer w0.2: R330.2@206.804,6.626 206.85,6.672 R329.2@206.85,7.681
  Top Layer w0.3: C261.1@206.804,5.644 R330.2@206.804,6.626 ; C261.1@206.821,5.628 206.898,5.551 206.898,5.119 207.073,4.943 207.249,4.943 207.425,4.767 Q3.3@207.425,4.093
NetC262_1: C262.1 R331.2 R333.1 U12.5 | length 8.2
  Top Layer w0.2: C262.1@265.4,56.5 C262.1@265.5,56.4
  Top Layer w0.3: U12.5@263.3,56.87 264.33,56.87 264.7,56.5 C262.1@265.4,56.5
  Top Layer w0.4: C262.1@265.4,56.5 265.55,56.65 265.55,57.05 266.121,57.621 R331.2@266.121,60.68 ; C262.1@265.5,56.4 265.5,55.9 265.7,55.7 R333.1@265.7,55.2
NetD1_1: D1.1 R81.2 | length 1.7
  Top Layer w0.4: R81.2@183.3,45.5 D1.1@185.03,45.5
NetD1_2: D1.2 J12.107 | length 19
  Top Layer w0.4: D1.2@186.2,45.5 v1(186.9,45.5) ; v1(203,44.2) 202.975,44.225 202.975,45.775 J12.107@203,45.8
  Bottom Layer w0.4: v1(186.9,45.5) 201.6,45.5 v1@203,44.1
NetD2_1: D2.1 R82.2 | length 1.9
  Top Layer w0.4: R82.2@183.2,43.5 183.4,43.3 184.1,43.3 184.15,43.35 184.95,43.35 D2.1@185,43.4
NetD2_2: D2.2 J12.109 | length 19.4
  Top Layer w0.4: D2.2@186.045,43.4 v1(186.9,43.4) ; v1(202.2,43.7) 202.175,43.725 202.175,45.675 J12.109@202.2,45.7
  Bottom Layer w0.4: v1(186.9,43.4) 191.5,43.4 192.874,44.774 197.526,44.774 198.805,43.495 201.692,43.495 201.797,43.6 201.952,43.6 202.012,43.66 202.143,43.66 v1@202.2,43.603
NetD4_1: D4.1 R210.2 | length 2.6
  Top Layer w0.2: D4.1@168.612,5.466 D4.1@168.682,5.396
  Top Layer w0.6: D4.1@168.612,5.466 R210.2@168.612,7.961
NetD6_1: D6.1 R217.2 | length 2.2
  Top Layer w0.2: D6.1@159.208,20.55 D6.1@159.283,20.625
  Top Layer w0.4: R217.2@157.083,20.55 D6.1@159.208,20.55
NetD7_L1_2: D7_L1.2 D9_L1.1
NetD7_L2_2: D7_L2.2 D9_L2.1
NetD7_L3_2: D7_L3.2 D9_L3.1
NetD7_N_2: D7_N.2 D9_N.1
NetD8_L1_1: D8_L1.1 D9_L1.2
NetD8_L1_2: D8_L1.2 R281_L1.2 R282_L1.2 | length 3.8
  Bottom Layer w0.254: R282_L1.2@92.97,150.686 92.97,147.803 R281_L1.2@92.917,147.75 92.917,147.661 R281_L1.2@93.44,147.138
  other v1: 94,147 95,147 96,147 97,147 98,147
NetD8_L2_1: D8_L2.1 D9_L2.2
